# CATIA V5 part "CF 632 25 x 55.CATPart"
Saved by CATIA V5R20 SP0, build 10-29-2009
Part number: CF 632 25 x 55
Definition: NONE
Nomenclature: CF 632 25 x 55
Source: Unknown
Description: CF 632 25 x 55
Bounding box of the stored display mesh (mm): x -13 to 42, y -22 to 22, z -22 to 22
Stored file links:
  C:\Users\Utente\Desktop\IO LAVORO\3D X SITO CF\X SITO\CF 632\CF 632 25 x 55.CATPart
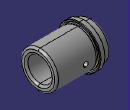
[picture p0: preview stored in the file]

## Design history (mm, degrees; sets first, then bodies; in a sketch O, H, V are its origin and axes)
Body1 "CF 632 25 x 55" (main body)
  Solid1: solid without history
